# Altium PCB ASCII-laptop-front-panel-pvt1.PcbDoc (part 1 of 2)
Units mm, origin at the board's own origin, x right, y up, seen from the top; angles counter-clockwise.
Board outline 38.68 x 84.1 mm, 4 copper layers (Top Layer, Internal Plane 1, Internal Plane 2, Bottom Layer), stack 1.573 mm thick; 37 components, 33 nets, 674 pads, 57 vias.
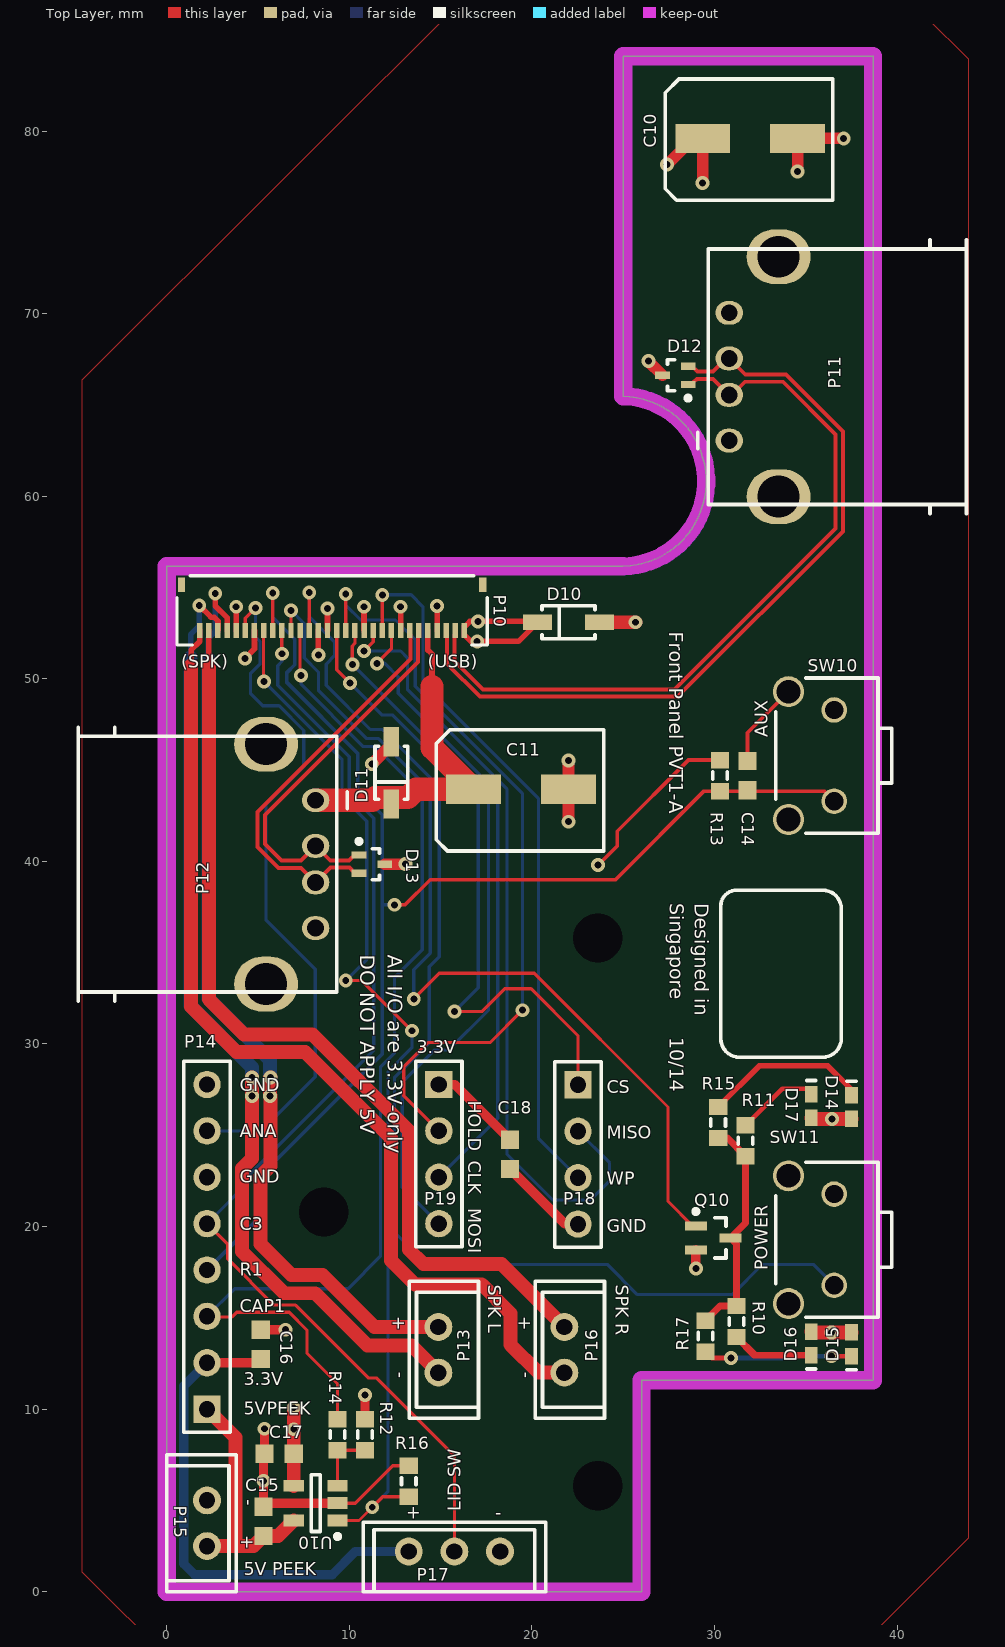
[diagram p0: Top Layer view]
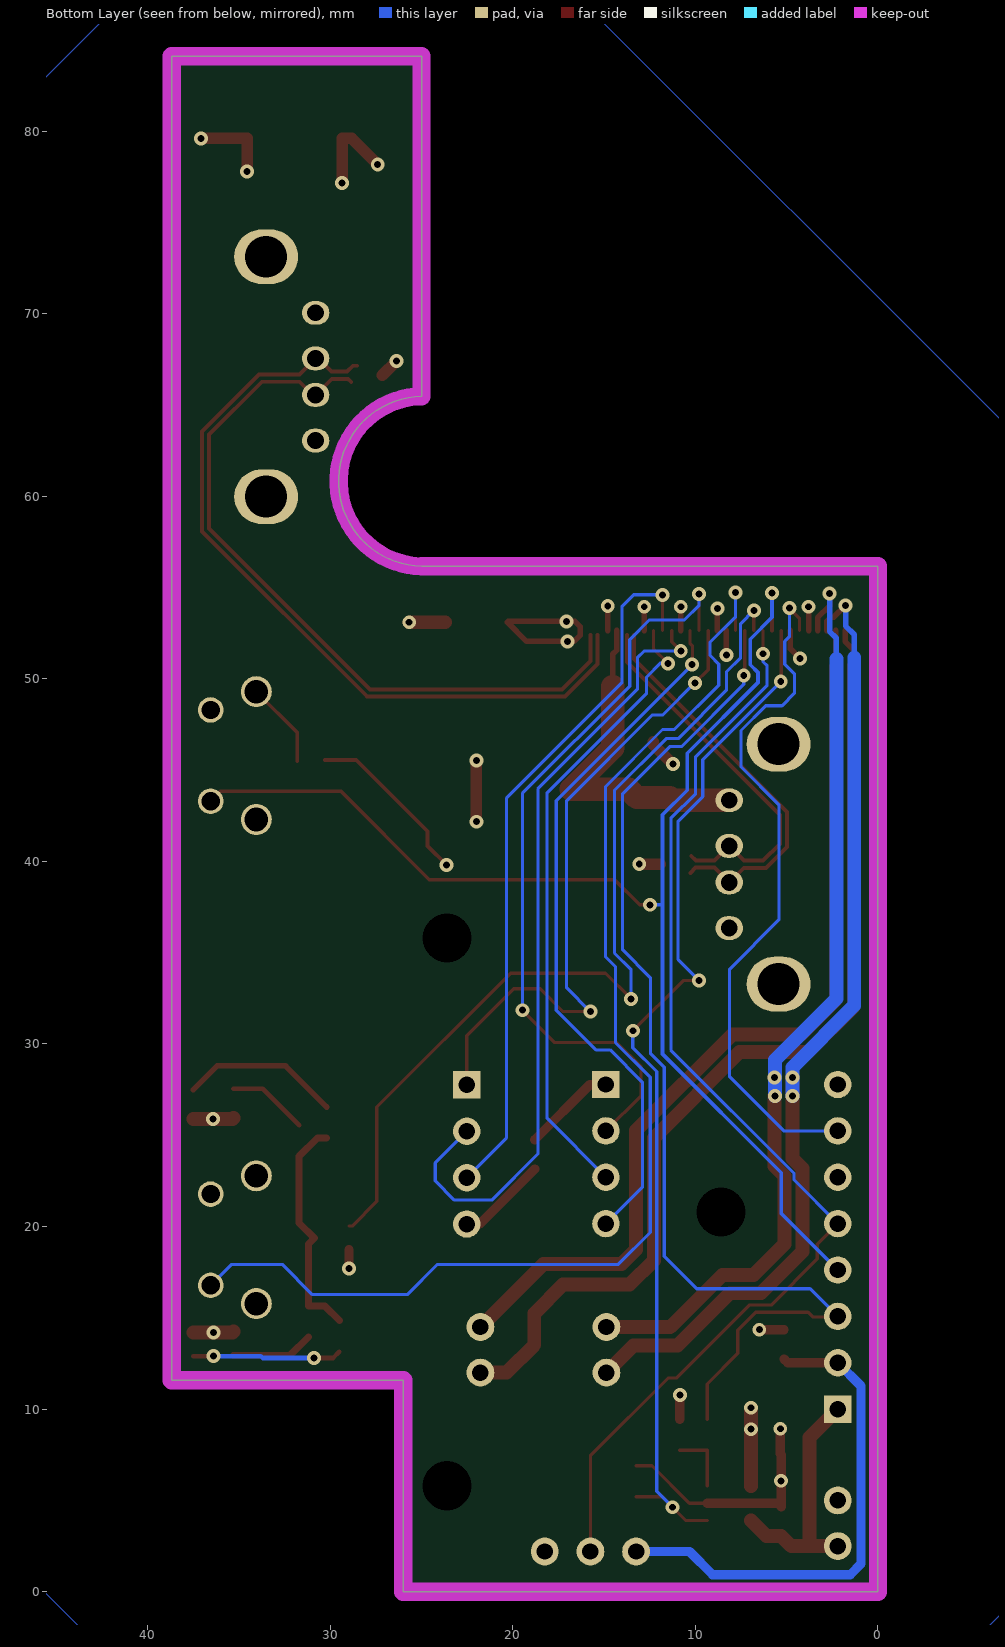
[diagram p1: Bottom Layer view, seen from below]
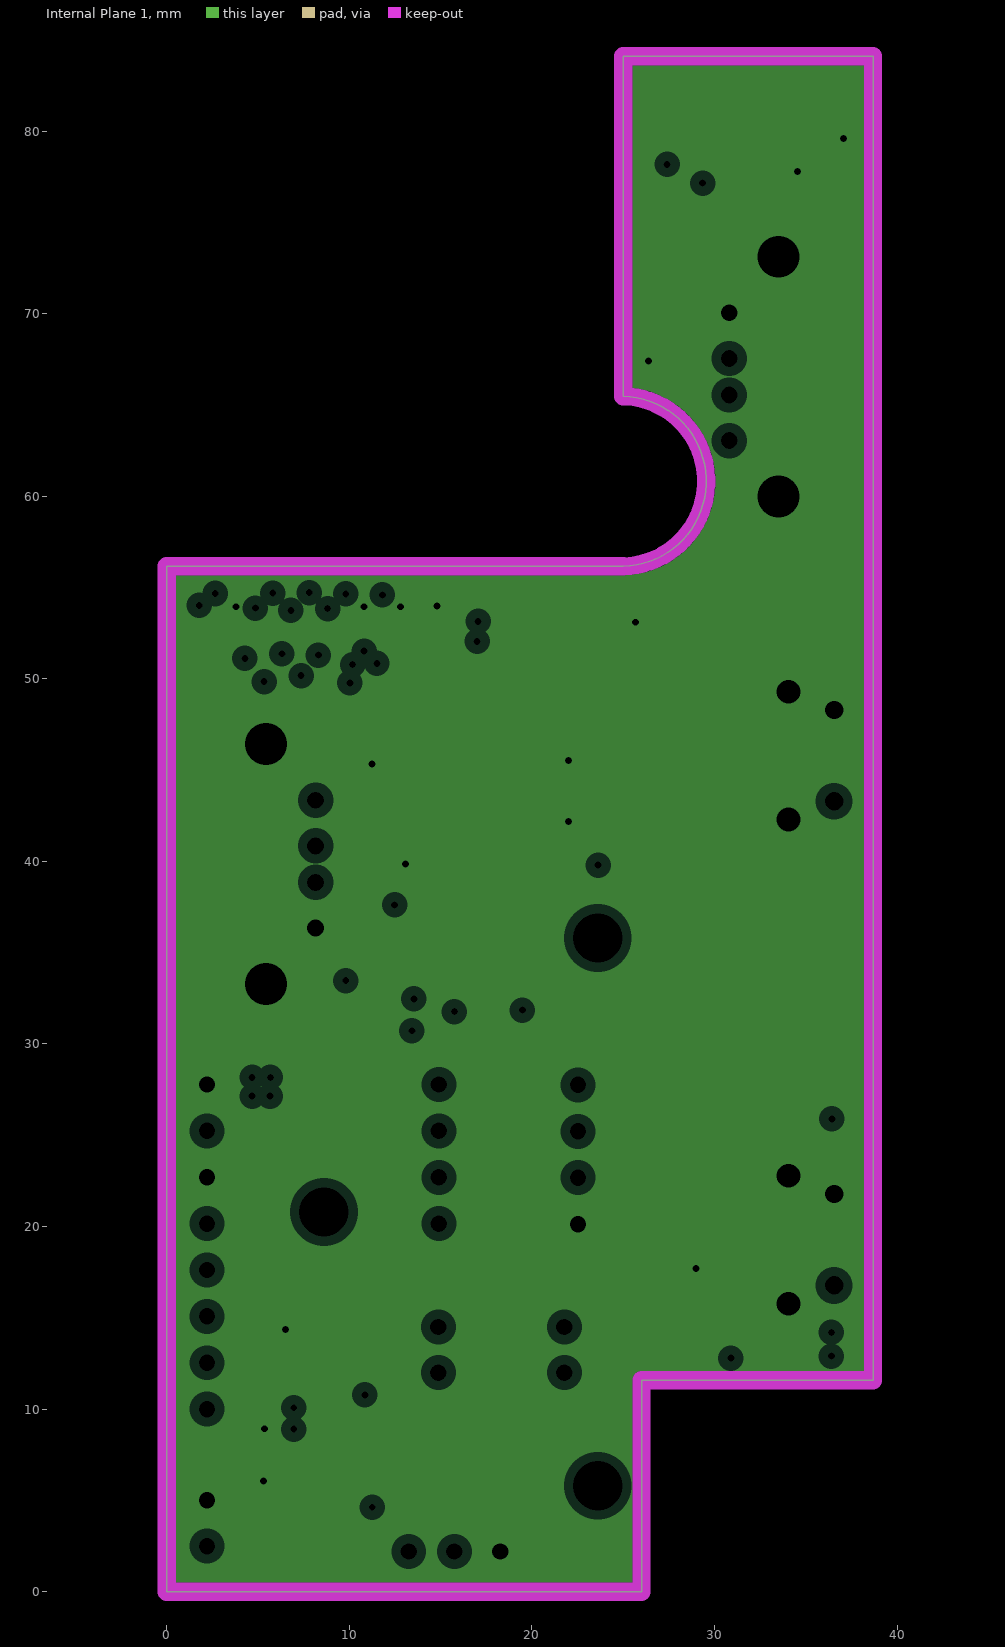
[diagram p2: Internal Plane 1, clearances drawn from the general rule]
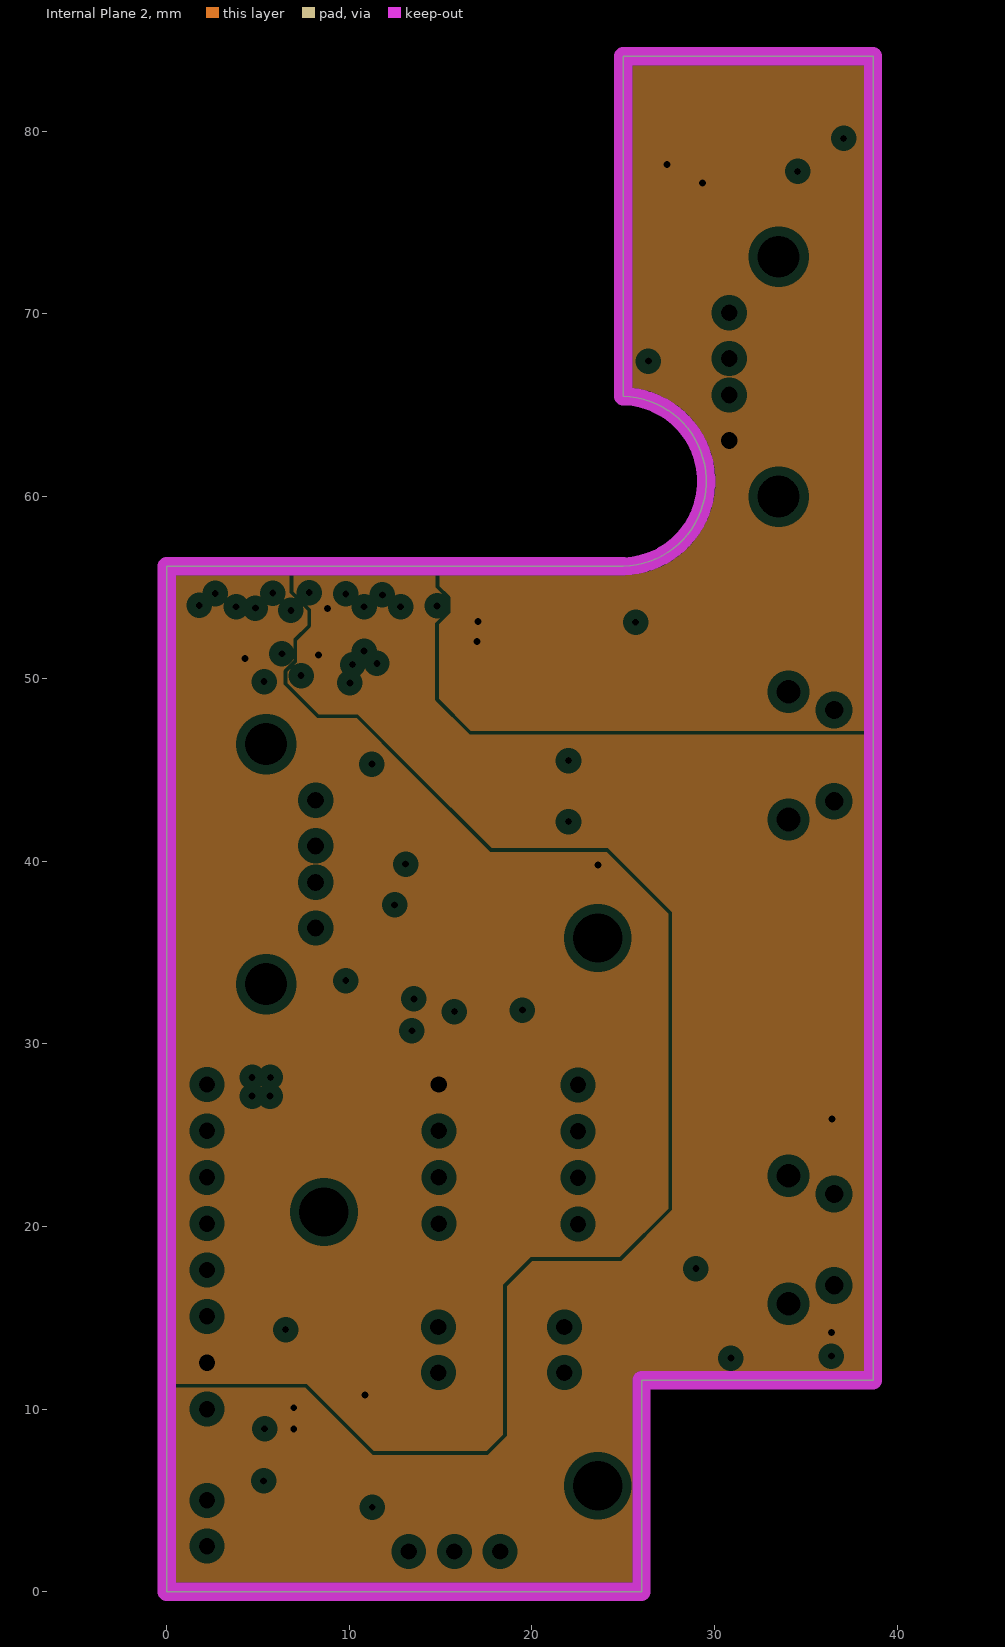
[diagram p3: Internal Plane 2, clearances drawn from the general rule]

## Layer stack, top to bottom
Top Solder: solder mask 0.0102, Solder Resist, Dk 3.5
Top Layer: signal copper 0.0356
Dielectric 1: core 0.165, FR-4, Dk 4.2
Internal Plane 1: plane copper 0.036, net GND
Dielectric 3: prepreg 1.1, Dk 4.2
Internal Plane 2: plane copper 0.036, net (Multiple Nets)
Dielectric 2: core 0.165, Dk 4.2
Bottom Layer: signal copper 0.0356
Bottom Solder: solder mask 0.0102, Solder Resist, Dk 3.5

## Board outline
0,0 0,56.161 24.997,56.161 ccw(c24.881,60.822) 24.997,65.483 24.997,82.115 24.997,84.099 38.685,84.099 38.685,11.581 26,11.581 26,0

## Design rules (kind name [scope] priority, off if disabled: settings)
AssemblyTestPointUsage [All] p0: scope1count=1 scope1_0_kind=Board scope1_0_value=Board scope2count=1 scope2_0_kind=Board scope2_0_value=Board commentlength=0
AssemblyTestpoint [All] p0: scope1count=1 scope1_0_kind=Board scope1_0_value=Board scope2count=1 scope2_0_kind=Board scope2_0_value=Board commentlength=0
Clearance Clearance_1 [All] p0 off: scope1count=1 scope1_0_kind=Board scope1_0_value=Board scope2count=1 scope2_0_kind=Board scope2_0_value=Board commentlength=88 gap=0.889 // Protel DXP Scope 2 Expression Was: InDifferentialPairClass('All Differential Pairs')
Clearance Clearance_NPTH [All] p0 off: scope1count=1 scope1_0_kind=Board scope1_0_value=Board scope2count=1 scope2_0_kind=Board scope2_0_value=Board commentlength=60 gap=0.381 // Protel DXP Scope 1 Expression Was: PadIsPlated = 'False'
Clearance [All] p0: scope1count=1 scope1_0_kind=Board scope1_0_value=Board scope2count=1 scope2_0_kind=Board scope2_0_value=Board commentlength=0 gap=0.178
Clearance Clearance_1 [InPoly vs InDifferentialPairClass('All Differential Pairs')] p1: gap=0.889
Clearance Clearance_NPTH [PadIsPlated = 'False'] p2: gap=0.381
Clearance [All] p3: gap=0.178
ComponentClearance [All] p0 off: scope1count=1 scope1_0_kind=Board scope1_0_value=Board scope2count=1 scope2_0_kind=Board scope2_0_value=Board commentlength=0 gap=0.254 collisioncheckmode=3
ComponentClearance [All] p1 off: gap=0.254 collisioncheckmode=3 verticalgap=0.254 showdistances=FALSE
DiffPairsRouting [All] p0: scope1count=1 scope1_0_kind=Board scope1_0_value=Board scope2count=1 scope2_0_kind=Board scope2_0_value=Board commentlength=0
DiffPairsRouting [All] p1: maxlimit=0.508 minlimit=0.178 mostfreqgap=0.178 toplayer_minwidth=0.216 toplayer_maxwidth=0.216 toplayer_prefwidth=0.216 bottomlayer_minwidth=0.216 bottomlayer_maxwidth=0.216 bottomlayer_prefwidth=0.216 maxuncoupledlength=12.7
FabricationTestPointUsage [All] p0: scope1count=1 scope1_0_kind=Board scope1_0_value=Board scope2count=1 scope2_0_kind=Board scope2_0_value=Board commentlength=0 valid=0 allowmultiple=FALSE
FabricationTestpoint [All] p0: scope1count=1 scope1_0_kind=Board scope1_0_value=Board scope2count=1 scope2_0_kind=Board scope2_0_value=Board commentlength=0 side=3 testpointundercomponent=TRUE minsize=1.016 maxsize=2.54 preferedsize=1.524 minholesize=0 maxholesize=1.016 preferedholesize=0.813 testpointgrid=0.025
FanoutControl Fanout_Default [All] p0: scope1count=1 scope1_0_kind=Board scope1_0_value=Board scope2count=1 scope2_0_kind=Board scope2_0_value=Board commentlength=30 // Fanout_Default (Default Rule)
FanoutControl Fanout_Small [All] p0 off: scope1count=1 scope1_0_kind=Board scope1_0_value=Board scope2count=1 scope2_0_kind=Board scope2_0_value=Board commentlength=84 // Protel DXP Scope 1 Expression Was: (CompPinCount < 5)   Fanout_Small (Default Rule)
FanoutControl Fanout_SOIC [All] p0 off: scope1count=1 scope1_0_kind=Board scope1_0_value=Board scope2count=1 scope2_0_kind=Board scope2_0_value=Board commentlength=71 // Protel DXP Scope 1 Expression Was: IsSOIC   Fanout_SOIC (Default Rule)
FanoutControl Fanout_LCC [All] p0 off: scope1count=1 scope1_0_kind=Board scope1_0_value=Board scope2count=1 scope2_0_kind=Board scope2_0_value=Board commentlength=69 // Protel DXP Scope 1 Expression Was: IsLCC   Fanout_LCC (Default Rule)
FanoutControl Fanout_BGA [All] p0 off: scope1count=1 scope1_0_kind=Board scope1_0_value=Board scope2count=1 scope2_0_kind=Board scope2_0_value=Board commentlength=69 // Protel DXP Scope 1 Expression Was: IsBGA   Fanout_BGA (Default Rule)
Height [All] p0: scope1count=1 scope1_0_kind=Board scope1_0_value=Board scope2count=1 scope2_0_kind=Board scope2_0_value=Board commentlength=0
HoleSize [All] p0: scope1count=1 scope1_0_kind=Board scope1_0_value=Board scope2count=1 scope2_0_kind=Board scope2_0_value=Board commentlength=0 absolutevalues=TRUE maxlimit=6.35 minlimit=0.025 maxpercent=80.000 minpercent=20.000
HoleSize [All] p1: absolutevalues=TRUE maxlimit=6.35 minlimit=0.025 maxpercent=80.000 minpercent=20.000
HoleToHoleClearance [All] p0: scope1count=1 scope1_0_kind=Board scope1_0_value=Board scope2count=1 scope2_0_kind=Board scope2_0_value=Board commentlength=0
LayerPairs [All] p0: scope1count=1 scope1_0_kind=Board scope1_0_value=Board scope2count=1 scope2_0_kind=Board scope2_0_value=Board commentlength=0 enforce=TRUE
MinimumSolderMaskSliver [All] p0 off: scope1count=1 scope1_0_kind=Board scope1_0_value=Board scope2count=1 scope2_0_kind=Board scope2_0_value=Board commentlength=0
MinimumSolderMaskSliver [All] p1 off: minsoldermaskwidth=0.254
NetAntennae [All] p0: scope1count=1 scope1_0_kind=Board scope1_0_value=Board scope2count=1 scope2_0_kind=Board scope2_0_value=Board commentlength=0
PasteMaskExpansion [All] p0: scope1count=1 scope1_0_kind=Board scope1_0_value=Board scope2count=1 scope2_0_kind=Board scope2_0_value=Board commentlength=0 expansion=0
PlaneClearance [All] p0: scope1count=1 scope1_0_kind=Board scope1_0_value=Board scope2count=1 scope2_0_kind=Board scope2_0_value=Board commentlength=0 clearance=0.508
PlaneClearance [All] p1: clearance=0.508
PlaneConnect [All] p0: scope1count=1 scope1_0_kind=Board scope1_0_value=Board scope2count=1 scope2_0_kind=Board scope2_0_value=Board commentlength=0 planeconnectstyle=Direct reliefexpansion=0.508 reliefentries=4 reliefconductorwidth=0.254 reliefairgap=0.254
PlaneConnect [All] p1: planeconnectstyle=Direct reliefexpansion=0.508 reliefentries=4 reliefconductorwidth=0.254 reliefairgap=0.254
PolygonConnect [All] p0: scope1count=1 scope1_0_kind=Board scope1_0_value=Board scope2count=1 scope2_0_kind=Board scope2_0_value=Board commentlength=0 connectstyle=Relief reliefconductorwidth=0.508 reliefentries=4 polygonreliefangle="90 Angle"
PolygonConnect [All] p1: connectstyle=Relief reliefconductorwidth=0.508 reliefentries=4 polygonreliefangle="90 Angle" airgapwidth=0.254
RoomDefinition connectors [All] p0 off: scope1count=1 scope1_0_kind=ComponentClass scope1_0_value=connectors scope2count=1 scope2_0_kind=Board scope2_0_value=Board commentlength=0 region_x1=30316014 region_y1=15196820 region_x2=32047180 region_y2=17472985 confinementstyle=ConfineIn
RoomDefinition connectors [InComponentClass('connectors')] p1 off: confinementstyle=ConfineIn formatcopy=TRUE lockcomponents=FALSE outline 35.697,1.458 31.3,1.458 31.3,7.239 35.697,7.239
RoutingCorners [All] p0: scope1count=1 scope1_0_kind=Board scope1_0_value=Board scope2count=1 scope2_0_kind=Board scope2_0_value=Board commentlength=0 cornerstyle=45-Degree minsetback=2.54 maxsetback=2.54
RoutingLayers [All] p0: scope1count=1 scope1_0_kind=Board scope1_0_value=Board scope2count=1 scope2_0_kind=Board scope2_0_value=Board commentlength=0 top layer=Automatic bottom layer=Automatic
RoutingPriority [All] p0: scope1count=1 scope1_0_kind=Board scope1_0_value=Board scope2count=1 scope2_0_kind=Board scope2_0_value=Board commentlength=0
RoutingTopology [All] p0: scope1count=1 scope1_0_kind=Board scope1_0_value=Board scope2count=1 scope2_0_kind=Board scope2_0_value=Board commentlength=0 topology=Shortest
RoutingVias [All] p0: scope1count=1 scope1_0_kind=Board scope1_0_value=Board scope2count=1 scope2_0_kind=Board scope2_0_value=Board commentlength=0 holewidth=0.381 width=0.762 viastyle="Through Hole" minholewidth=0.381 minwidth=0.762 maxholewidth=0.381 maxwidth=0.762
RoutingVias [All] p1: holewidth=0.381 width=0.762 viastyle="Through Hole" minholewidth=0.381 minwidth=0.762 maxholewidth=0.381 maxwidth=0.762
ShortCircuit [All] p0: scope1count=1 scope1_0_kind=Board scope1_0_value=Board scope2count=1 scope2_0_kind=Board scope2_0_value=Board commentlength=0 allowed=FALSE
SilkToBoardRegionClearance [All] p0 off: scope1count=1 scope1_0_kind=Board scope1_0_value=Board scope2count=1 scope2_0_kind=Board scope2_0_value=Board commentlength=0
SilkToBoardRegionClearance [All] p1 off:
SilkToSilkClearance [All] p0 off: scope1count=1 scope1_0_kind=Board scope1_0_value=Board scope2count=1 scope2_0_kind=Board scope2_0_value=Board commentlength=0
SilkToSilkClearance [All] p1 off: silktosilkclearance=0.254
SilkToSolderMaskClearance [All] p0 off: scope1count=1 scope1_0_kind=Board scope1_0_value=Board scope2count=1 scope2_0_kind=Board scope2_0_value=Board commentlength=44 // Protel DXP Scope 1 Expression Was: IsPad
SilkToSolderMaskClearance [IsPad] p1 off: minsilkscreentomaskgap=0.254 clearancetoexposedcopper=TRUE
SolderMaskExpansion [All] p0: scope1count=1 scope1_0_kind=Board scope1_0_value=Board scope2count=1 scope2_0_kind=Board scope2_0_value=Board commentlength=0 expansion=0.076
SolderMaskExpansion [All] p1: expansion=0.076
UnRoutedNet [All] p0: scope1count=1 scope1_0_kind=Board scope1_0_value=Board scope2count=1 scope2_0_kind=Board scope2_0_value=Board commentlength=0
Width [All] p0: scope1count=1 scope1_0_kind=Board scope1_0_value=Board scope2count=1 scope2_0_kind=Board scope2_0_value=Board commentlength=0 maxlimit=2.54 minlimit=0.178 preferedwidth=0.254
Width [All] p1: maxlimit=2.54 minlimit=0.178 preferedwidth=0.254 minimp=50.000000 maximp=50.000000 favimp=50.000000
20 further rules are at their usual default settings.

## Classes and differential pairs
net class USB_NETS: USB_KBD_N USB_KBD_P USB_MOUSE_N USB_MOUSE_P
differential pair USB_MOUSE: +USB_MOUSE_P -USB_MOUSE_N
differential pair " ": +USB_KBD_P -USB_KBD_N

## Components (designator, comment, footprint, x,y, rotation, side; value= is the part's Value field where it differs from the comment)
C10 "100uF, 10V, VS D" ALCAP_D 31.95,79.6 r180 top
C11 "100uF, 10V, VS D" ALCAP_D 19.4,43.95 r180 top
C14 "0.1uF, 25V, X5R" CAPC1608N 31.8,44.7 r90 top
C15 "10uF, 10V, X5R, 20%" CAPC1608N 5.3,3.85 r90 top
C16 "10uF, 10V, X5R, 20%" CAPC1608N 5.15,13.55 r90 top
C17 "1.0uF, 25V, 20% X5R" CAPC1608N 6.15,7.55 r180 top
C18 "0.1uF, 25V, X5R" CAPC1608N 18.8,23.95 r270 top
D10 "RSA5M" SOD123/X.85 22,53.1 r0 top
D11 "RSA5M" SOD123/X.85 12.3,44.85 r90 top
D12 "RCLAMP0502B" SOT-523 27.85,66.625 r180 top
D13 "RCLAMP0502B" SOT-523 11.225,39.85 r0 top
D14 "WHITE 0402" CD1005-0402 37.5,26.55 r90 top
D15 "WHITE 0402" CD1005-0402 37.5,13.55 r270 top
D16 "WHITE 0402" CD1005-0402 35.3,13.6 r270 top
D17 "WHITE 0402" CD1005-0402 35.3,26.6 r90 top
P10 "HRS FH34SRJ-30S-0.5SH(99)" HRS_FH34SRJ-30S-0.5SH 9.55,52.65 r180 top
P11 "AUK USB-1X04-SR-BK-S-H" USB_TYPEA_TH_SINGLE 30.8,66.55 r90 top
P12 "AUK USB-1X04-SR-BK-S-H" USB_TYPEA_TH_SINGLE 8.15,39.85 r270 top
P13 "JST B2B-EH-A" JST_B2B_EH_A 14.875,12 r90 top
P14 "Header 8" HDR1X8 2.2,10 r90 top
P15 "JST B2B-EH-A" JST_B2B_EH_A 2.2,5 r270 top
P16 "JST B2B-EH-A" JST_B2B_EH_A 21.775,12 r90 top
P17 "JST B3B-EH-A" JST_B3B_EH_A 13.25,2.2 r0 top
P18 "Header 4" HDR1X4 22.52,27.757 r270 top
P19 "Header 4" HDR1X4 14.9,27.78 r270 top
Q10 "2N7002W" SOT323-3AN 29.925,19.375 r0 top
R10 "1k, 1%" RESC1608N 31.2,14.8 r270 top
R11 "1k, 1%" RESC1608N 31.7,24.7 r90 top
R12 "10k, 1%" RESC1608N 10.85,8.6 r270 top
R13 "10k, 1%" RESC1608N 30.3,44.7 r270 top
R14 "0 ohm (DNP)" RESC1608N 9.35,8.6 r90 top
R15 "1k, 1%" RESC1608N 30.2,25.7 r90 top
R16 "10k, 1%" RESC1608N 13.25,6.05 r90 top
R17 "1k, 1%" RESC1608N 29.5,14 r270 top
SW10 "PTS635-V-L-31" PTS635-V-X-31 36.551,45.796 r90 top
SW11 "PTS635-V-L-31" PTS635-V-X-31 36.551,19.279 r90 top
U10 "RT9706" SOT23-5AN 8.15,4.85 r180 top

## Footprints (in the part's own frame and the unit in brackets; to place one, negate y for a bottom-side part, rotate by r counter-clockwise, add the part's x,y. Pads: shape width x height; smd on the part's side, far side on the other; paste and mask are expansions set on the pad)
ALCAP_D [mm]
  rect 3x1.6 smd: 1(2.6,0) 2(-2.6,0)
  silkscreen extent -4.52,-3.25 4.65,3.38
CAPC1608N [mm] "Chip Capacitor, Body 1.6x0.8mm, IPC Medium Density"
  rect 1x1 smd: 1(-0.8,0) 2(0.8,0)
CD1005-0402 [mm] "Chip Diode; Body 1.0 x 0.5 mm (LxW typ)"
  rect 0.9x0.7 smd: 1(-0.65,0) 2(0.65,0)
  silkscreen extent 1.4,-0.25 1.4,0.25
HDR1X4 [mm] "Connector; Header; 4 Position"
  rect 1.5x1.5 hole 0.9: 1(0,0)
  round 1.5 hole 0.9: 2(2.54,0) 3(5.08,0) 4(7.62,0)
  silkscreen extent -1.27,-1.27 8.89,1.27
HDR1X8 [mm] "Connector; Header; 8 Position"
  rect 1.5x1.5 hole 0.9: 1(0,0)
  round 1.5 hole 0.9: 2(2.54,0) 3(5.08,0) 4(7.62,0) 5(10.16,0) 6(12.7,0) 7(15.24,0) 8(17.78,0)
  silkscreen extent -1.27,-1.27 19.05,1.27
HRS_FH34SRJ-30S-0.5SH [mm] "HRS 30-pin 0.5mm FFC/FPC"
  rect 0.4x0.8 smd: 0(-7.75,-2.5) 0(8.75,-2.5)
  rect 0.3x0.8 smd mask+0.07: 1(7.75,0) 2(7.25,0) 3(6.75,0) 4(6.25,0) 5(5.75,0) 6(5.25,0) 7(4.75,0) 8(4.25,0) 9(3.75,0) 10(3.25,0) 11(2.75,0) 12(2.25,0) 13(1.75,0) 14(1.25,0) 15(0.75,0) 16(0.25,0) 17(-0.25,0) 18(-0.75,0) 19(-1.25,0) 20(-1.75,0) 21(-2.25,0) 22(-2.75,0) 23(-3.25,0) 24(-3.75,0) 25(-4.25,0) 26(-4.75,0) 27(-5.25,0) 28(-5.75,0) 29(-6.25,0) 30(-6.75,0)
  silkscreen extent -8,-3 9,0.8
JST_B2B_EH_A [mil] "2-pin 2.5mm low cost connector"
  round 60 hole 35.43: 1(0,0) 2(98.42,0)
  silkscreen extent -98,-87 197,63
JST_B3B_EH_A [mil] "3-pin 2.5mm low cost connector"
  round 60 hole 35.43: 1(0,0) 2(98.43,0) 3(196.85,0)
  silkscreen extent -98,-87 295,63
PTS635-V-X-31 [mm] "Tact switch, right angle, through hole"
  round 1.7 hole 1.3 mask+0.07: 0(-3.5,2.5) 0(3.5,2.5)
  round 1.4 hole 1 mask+0.07: 1(-2.5,0) 2(2.5,0)
  silkscreen extent -4.25,-3.15 4.25,3.2
RESC1608N [mm] "Chip Resistor, Body 1.6x0.8mm, IPC Medium Density"
  rect 0.9x1 smd: 1(-0.85,0) 2(0.85,0)
  silkscreen extent -0.2,-0.4 0.2,0.4
SOD123/X.85 [mm] "SOD-123; 2 Leads; Body 2.7 x 1.6 mm, (LxW)"
  rect 1.6x0.85 smd: 1(-1.7,0) 2(1.7,0)
  silkscreen extent -1.45,-0.9 1.45,0.9
SOT23-5AN [mm] "SOT23, 5-Leads, Body 2.9x1.6mm, Pitch 0.95mm, Lead Span 2.8mm, IPC Medium Density"
  rect 1.1x0.65 smd mask+0.075: 1(-1.2,0.95) 2(-1.2,0) 3(-1.2,-0.95) 4(1.2,-0.95) 5(1.2,0.95)
  silkscreen extent -1.33,-1.55 0.25,1.95
SOT323-3AN [mm] "SOT323, 3-Leads, Body 2.0x1.3mm, Pitch 0.65mm, Lead Span 2.1mm, IPC Medium Density"
  rect 1.2x0.5 smd: 1(-0.95,0.65) 2(-0.95,-0.65) 3(0.95,0)
  silkscreen extent -1.07,-1.1 0.7,1.57
SOT-523 [mm] "SOT523/SC75, 3-Leads, Body 1.7x1.8mm (max), Pitch 0.50mm, IPC Medium Density"
  rect 0.8x0.4 smd: 1(-0.7,0.5) 2(-0.7,-0.5) 3(0.7,0)
  silkscreen extent -0.82,-0.85 0.43,1.37
USB_TYPEA_TH_SINGLE [mm] "USB Type A Female Through Hole, Right Angle"
  oval 3x3.5 hole 2.3 mask+0.07: 0(-6.57,-2.71) 0(6.57,-2.71)
  oval 1.3x1.5 hole 0.92 mask+0.07: 1(-3.5,0) 2(-1,0) 3(1,0) 4(3.5,0)
  silkscreen extent -7.5,-13 7.5,1.73

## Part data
C10 C11: library part "Cap Pol3", "Polarized Capacitor (Surface Mount)"
C14 C15 C16 C17 C18: library part "Cap Semi", "Capacitor (Semiconductor SIM Model)"
D10 D11: library part Tranzorb, "Tranzorb"
D12 D13: "2-channel ESD/CDE protection device for 5V devices"
D14 D15 D16 D17: library part LED2, "Green R/A LED, 0603 package"
P10: library part "Header 30", "Header, 30-Pin"
P11 P12: library part "Header 4", "Header, 4-Pin"
P13 P15 P16: library part "Header 2", "Header, 2-Pin"
P14: "Header, 8-Pin"
P17: library part "Header 3", "Header, 3-Pin"
P18 P19: "Header, 4-Pin"
Q10: library part MOSFET-N, "N-Channel MOSFET"
R10 R11 R12 R13 R14 R15 R16 R17: library part Res1, "Resistor"
SW10 SW11: library part SW-PB
U10: "IC LIN SW W/FLAG 500MA 2.0-5.5V SOT23-5"

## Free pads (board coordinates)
  round 2.5 hole 2.7 unplated mask+1.5: 0(8.6,20.8) 0(23.6,5.8) 0(23.6,35.8)
  rect 0.051x0.254 on Top Overlay: 1(30.823,33.571) 1(30.873,36.162) 1(31.331,30.167) 1(31.381,30.167) 1(31.432,30.167) 1(31.534,30.624) 1(31.889,37.736) 1(31.94,37.686) 1(31.991,34.434) 1(31.991,37.635) 1(32.042,37.584) 1(32.093,31.031) 1(32.093,37.533) 1(32.143,37.482) 1(32.194,32.91) 1(32.194,37.432) 1(32.347,37.33) 1(32.397,31.894) 1(32.397,37.279) 1(32.651,31.844) 1(32.702,31.844) 1(32.753,31.844) 1(32.804,31.844) 1(32.855,31.844) 1(32.905,31.844) 1(32.905,33.672) 1(32.956,31.844) 1(32.956,33.622) 1(33.261,35.196) 1(33.312,35.247) 1(33.363,35.298) 1(33.413,36.771) 1(33.515,31.64) 1(33.617,31.59) 1(33.667,31.539) 1(34.531,36.009) 1(34.937,35.45) 1(34.988,33.266) 1(34.988,35.349) 1(35.039,35.298) 1(35.09,31.59) 1(35.09,35.196) 1(35.09,37.635) 1(35.141,30.98) 1(35.141,35.146) 1(35.141,37.584) 1(35.191,31.437) 1(35.191,35.095) 1(35.191,37.482) 1(35.242,31.386) 1(35.242,36.365) 1(35.242,37.381) 1(35.293,36.365) 1(35.293,37.33) 1(35.344,36.416) 1(35.344,37.228) 1(35.395,32.707) 1(35.395,36.466) 1(35.395,37.178) 1(35.445,32.656) 1(35.445,36.517) 1(35.445,37.127) 1(35.496,32.555) 1(35.496,37.076) 1(35.547,32.504) 1(35.547,36.67) 1(35.547,37.025) 1(35.598,32.453) 1(35.649,32.402) 1(35.699,33.317) 1(35.699,36.873) 1(35.75,33.368) 1(35.75,36.822) 1(35.801,36.771) 1(35.903,33.571) 1(35.903,34.536) 1(35.903,36.72) 1(35.953,36.67) 1(36.055,36.619) 1(36.106,34.434) 1(36.157,33.114) 1(36.207,33.164) 1(36.309,32.402) 1(36.309,33.317) 1(36.309,34.993) 1(36.36,30.675) 1(36.36,32.453) 1(36.36,34.993) 1(36.411,35.044) 1(36.461,30.777)
  rect 0.051x0.203 on Top Overlay: 1(30.823,36.187) 1(31.483,30.193) 1(31.483,30.65) 1(31.839,37.762) 1(31.94,34.46) 1(33.413,31.717) 1(33.413,35.374) 1(33.464,30.599) 1(33.464,31.666) 1(33.464,36.797) 1(33.566,31.615) 1(34.226,31.31) 1(34.582,32.377) 1(34.887,35.527) 1(34.937,30.751) 1(35.039,31.666) 1(35.141,31.513) 1(35.191,31.056) 1(35.191,36.339) 1(35.242,35.019) 1(35.293,31.31) 1(35.293,34.968) 1(35.344,31.259) 1(35.344,34.917) 1(35.395,31.209) 1(35.395,34.866) 1(35.445,31.158) 1(35.496,31.107) 1(35.547,31.056) 1(35.598,31.005) 1(35.649,30.955) 1(35.649,33.291) 1(35.699,30.904) 1(35.699,32.326) 1(35.699,35.374) 1(35.75,32.275) 1(35.75,34.612) 1(35.801,32.225) 1(35.801,34.612) 1(35.852,31.463) 1(35.852,32.174) 1(35.852,34.561) 1(35.852,35.273) 1(35.852,36.746) 1(35.903,35.222) 1(35.953,34.511) 1(36.004,31.564) 1(36.004,34.46) 1(36.004,35.171) 1(36.004,36.644) 1(36.055,34.46) 1(36.055,35.12) 1(36.106,33.088) 1(36.207,35.069) 1(36.258,32.377) 1(36.258,35.019) 1(36.411,32.123) 1(36.411,32.529) 1(36.461,32.174) 1(36.563,32.275)
  rect 0.051x0.457 on Top Overlay: 1(30.873,33.469) 1(31.077,32.91) 1(31.127,32.809) 1(31.178,32.707) 1(32.296,34.485) 1(32.347,34.485) 1(32.397,34.536) 1(32.448,34.536) 1(32.499,34.587) 1(32.55,34.587) 1(32.601,34.638) 1(32.651,34.688) 1(32.753,34.739) 1(33.312,36.72) 1(33.413,33.012) 1(33.921,31.336) 1(34.328,32.402) 1(34.379,32.352) 1(34.429,35.908)
  rect 0.051x1.372 on Top Overlay: 1(30.924,30.777)
  rect 0.051x0.508 on Top Overlay: 1(30.924,33.342) 1(30.975,33.19) 1(31.026,33.037) 1(31.178,30.142) 1(33.21,36.746) 1(33.261,36.746) 1(33.972,31.259) 1(34.429,32.326) 1(35.09,33.241) 1(35.598,36.847) 1(35.699,34.815) 1(35.801,35.171)
  rect 0.051x0.356 on Top Overlay: 1(30.924,36.162) 1(31.28,30.167) 1(31.28,31.488) 1(31.28,36.009) 1(31.432,32.352) 1(31.483,32.301) 1(31.534,32.25) 1(31.585,32.25) 1(31.635,32.199) 1(31.686,30.675) 1(31.686,32.148) 1(31.788,32.098) 1(31.889,32.047) 1(31.991,30.929) 1(32.042,30.98) 1(32.093,34.434) 1(32.702,37.076) 1(32.855,36.974) 1(32.956,36.924) 1(33.007,34.942) 1(33.058,34.993) 1(33.058,36.873) 1(33.109,33.418) 1(33.159,33.368) 1(33.363,36.771) 1(33.464,33.012) 1(33.566,32.961) 1(33.617,32.91) 1(33.667,32.86) 1(33.718,32.809) 1(33.769,32.809) 1(33.82,31.437) 1(33.82,32.758) 1(33.871,31.386) 1(33.871,32.707) 1(33.921,32.707) 1(33.972,32.656) 1(34.125,32.555) 1(34.328,35.958) 1(34.48,35.958) 1(34.531,32.352) 1(35.039,30.777) 1(35.649,36.873) 1(35.75,34.993) 1(35.801,30.777) 1(35.852,33.52) 1(36.258,33.266) 1(36.411,30.726)
  rect 0.051x1.473 on Top Overlay: 1(30.975,30.777)
  rect 0.051x0.406 on Top Overlay: 1(30.975,36.136) 1(31.178,31.412) 1(31.229,30.142) 1(31.229,31.463) 1(31.229,32.631) 1(31.28,32.529) 1(31.28,36.593) 1(31.331,32.479) 1(31.381,32.428) 1(31.737,30.701) 1(31.788,30.701) 1(31.839,30.751) 1(31.889,30.802) 1(31.94,30.853) 1(32.143,34.46) 1(32.194,34.46) 1(32.245,34.46) 1(32.702,34.714) 1(32.804,34.765) 1(32.855,34.815) 1(32.905,34.866) 1(32.956,34.917) 1(33.007,36.898) 1(33.109,36.847) 1(33.159,36.797) 1(34.125,31.31) 1(34.175,32.529) 1(34.226,32.479) 1(34.277,32.428) 1(34.379,35.933) 1(34.48,32.326) 1(35.039,33.241) 1(35.09,30.802) 1(35.445,34.765) 1(35.496,34.714) 1(35.649,34.765) 1(35.75,30.802) 1(36.055,37.305) 1(36.106,35.019) 1(36.207,36.644)
  rect 0.051x1.626 on Top Overlay: 1(31.026,30.751)
  rect 0.051x0.559 on Top Overlay: 1(31.026,36.162)
  rect 0.051x1.676 on Top Overlay: 1(31.077,30.777)
  rect 0.051x0.61 on Top Overlay: 1(31.077,36.187) 1(35.141,33.19) 1(35.903,31.31) 1(36.207,34.561)
  rect 0.051x1.727 on Top Overlay: 1(31.127,30.751) 1(34.074,31.92)
  rect 0.051x0.762 on Top Overlay: 1(31.127,36.212) 1(36.106,37.127)
  rect 0.051x0.914 on Top Overlay: 1(31.178,36.289) 1(36.157,34.714)
  rect 0.051x0.965 on Top Overlay: 1(31.229,36.314)
  rect 0.051x0.305 on Top Overlay: 1(31.331,31.513) 1(31.331,35.984) 1(31.381,31.513) 1(31.381,35.984) 1(31.432,31.513) 1(31.432,35.984) 1(31.483,31.513) 1(31.483,35.984) 1(31.534,31.513) 1(31.534,35.984) 1(31.585,30.65) 1(31.585,31.513) 1(31.585,35.984) 1(31.635,30.65) 1(31.635,31.513) 1(31.635,35.984) 1(31.686,31.513) 1(31.686,35.984) 1(31.737,31.513) 1(31.737,32.123) 1(31.737,35.984) 1(31.788,31.513) 1(31.788,35.984) 1(31.839,31.513) 1(31.839,32.072) 1(31.839,35.984) 1(31.889,31.513) 1(31.889,35.984) 1(31.94,31.513) 1(31.94,32.021) 1(31.94,35.984) 1(31.991,31.513) 1(31.991,32.021) 1(31.991,35.984) 1(32.042,31.513) 1(32.042,31.971) 1(32.042,34.46) 1(32.042,35.984) 1(32.093,31.513) 1(32.093,31.971) 1(32.093,35.984) 1(32.143,31.513) 1(32.143,31.971) 1(32.143,35.984) 1(32.194,31.513) 1(32.194,31.92) 1(32.194,35.984) 1(32.245,31.513) 1(32.245,31.92) 1(32.245,32.885) 1(32.245,35.984) 1(32.245,37.406) 1(32.296,30.599) 1(32.296,31.513) 1(32.296,31.92) 1(32.296,32.885) 1(32.296,35.984) 1(32.296,37.355) 1(32.347,30.599) 1(32.347,31.513) 1(32.347,31.92) 1(32.347,32.885) 1(32.347,35.984) 1(32.397,30.599) 1(32.397,31.513) 1(32.397,32.885) 1(32.397,35.984) 1(32.448,35.984) 1(32.448,37.254) 1(32.499,35.984) 1(32.499,37.203) 1(32.55,30.599) 1(32.55,31.869) 1(32.55,32.885) 1(32.55,35.984) 1(32.55,37.152) 1(32.601,30.599) 1(32.601,31.869) 1(32.601,32.885) 1(32.601,35.984) 1(32.601,37.152) 1(32.651,30.599) 1(32.651,32.885) 1(32.651,35.984) 1(32.651,37.101) 1(32.702,30.599) 1(32.702,32.885) 1(32.702,35.984) 1(32.753,30.599) 1(32.753,32.885) 1(32.753,35.984) 1(32.753,37.051) 1(32.804,30.599) 1(32.804,32.885) 1(32.804,35.984) 1(32.804,37) 1(32.855,30.599) 1(32.855,32.885) 1(32.855,35.984) 1(32.905,30.599) 1(32.905,32.885) 1(32.905,35.984) 1(32.905,36.949) 1(32.956,30.599) 1(32.956,32.885) 1(32.956,35.984) 1(33.007,30.599) 1(33.007,31.818) 1(33.007,32.885) 1(33.007,33.545) 1(33.007,35.984) 1(33.058,30.599) 1(33.058,31.818) 1(33.058,32.885) 1(33.058,33.495) 1(33.058,35.984) 1(33.109,30.599) 1(33.109,31.818) 1(33.109,32.885) 1(33.109,35.069) 1(33.109,35.984) 1(33.159,30.599) 1(33.159,31.818) 1(33.159,32.885) 1(33.159,35.12) 1(33.159,35.984) 1(33.21,30.599) 1(33.21,31.818) 1(33.21,32.885) 1(33.21,33.291) 1(33.21,35.171) 1(33.21,35.984) 1(33.261,35.984) 1(33.312,35.984) 1(33.363,35.984) 1(33.413,30.599) 1(33.413,35.984) 1(33.464,35.984) 1(33.515,32.987) 1(33.515,35.984) 1(33.566,35.984) 1(33.617,35.984) 1(33.667,35.984) 1(33.718,31.513) 1(33.718,35.984) 1(33.769,31.463) 1(33.769,35.984) 1(33.82,35.984) 1(33.871,35.984) 1(33.921,35.984) 1(33.972,35.984) 1(34.023,35.984) 1(34.074,35.984) 1(34.125,35.984) 1(34.175,31.31) 1(34.175,35.984) 1(34.226,35.984) 1(34.277,35.984) 1(34.988,30.751) 1(35.191,32.987) 1(35.242,32.936) 1(35.293,32.834) 1(35.344,32.783) 1(35.496,36.593) 1(35.547,34.714) 1(35.598,34.714) 1(35.801,33.393) 1(35.852,30.751) 1(35.903,30.751) 1(36.055,30.142) 1(36.106,36.543) 1(36.512,32.225)
  rect 0.051x0.102 on Top Overlay: 1(31.432,30.65) 1(32.143,32.987) 1(32.855,33.698) 1(33.515,36.847) 1(34.887,30.751) 1(35.039,37.711) 1(35.191,33.444) 1(35.242,33.444) 1(35.445,35.628) 1(36.055,31.615) 1(36.055,32.021) 1(36.157,32.326) 1(36.207,37.508) 1(36.258,36.593) 1(36.461,32.58)
  rect 0.051x0.152 on Top Overlay: 1(31.534,30.167) 1(31.585,30.167) 1(31.635,30.167) 1(31.686,30.167) 1(31.737,30.167) 1(31.788,30.167) 1(31.839,30.167) 1(31.889,30.167) 1(31.889,34.434) 1(31.94,30.167) 1(32.143,31.082) 1(32.245,30.675) 1(33.464,35.4) 1(33.515,30.624) 1(34.582,36.06) 1(34.633,32.402) 1(34.937,33.266) 1(35.141,30.675) 1(35.141,36.314) 1(35.191,30.675) 1(35.242,30.675) 1(35.293,30.675) 1(35.344,30.675) 1(35.395,30.675) 1(35.445,30.675) 1(35.496,30.675) 1(35.496,35.603) 1(35.547,30.675) 1(35.547,35.552) 1(35.598,30.675) 1(35.598,35.501) 1(35.649,30.675) 1(35.649,35.45) 1(35.699,30.675) 1(35.75,35.349) 1(35.903,32.148) 1(35.953,32.098) 1(35.953,35.196) 1(36.004,32.047) 1(36.004,37.33) 1(36.055,30.675) 1(36.055,33.063) 1(36.106,30.675) 1(36.157,30.675) 1(36.207,30.675) 1(36.207,32.352) 1(36.258,30.675) 1(36.258,34.434) 1(36.309,30.675) 1(36.36,32.098) 1(36.461,35.095)
  rect 0.051x2.591 on Top Overlay: 1(32.448,31.742) 1(32.499,31.742)
  rect 0.051x2.997 on Top Overlay: 1(33.261,31.894) 1(33.312,31.844)
  rect 0.051x2.946 on Top Overlay: 1(33.363,31.818)
  rect 0.051x0.051 on Top Overlay: 1(33.515,35.4) 1(34.277,31.336) 1(34.836,35.552) 1(34.988,31.691) 1(35.242,31.082) 1(36.309,32.098)
  rect 0.051x1.778 on Top Overlay: 1(34.023,31.894) 1(35.953,30.777)
  rect 0.051x1.27 on Top Overlay: 1(36.004,30.574)
  rect 0.051x1.118 on Top Overlay: 1(36.157,37)

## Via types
v1: diameter 0.762, hole 0.381, Top Layer to Bottom Layer, tented top, 57 vias

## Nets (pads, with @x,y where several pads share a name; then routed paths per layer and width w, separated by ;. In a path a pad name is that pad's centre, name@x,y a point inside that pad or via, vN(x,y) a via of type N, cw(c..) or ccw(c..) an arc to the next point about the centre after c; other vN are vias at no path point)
CHG_PWRSWITCH: P10.13 SW11.1 | length 68.5
  Top Layer w0.178: P10.13@7.8,52.65 v1(7.8,54.725)
  Bottom Layer w0.178: v1(7.8,54.725) 7.8,53.4 9.2,52 9.2,51.284 8.725,50.809 8.725,49.65 11.15,47.225 11.8,47.225 14.925,44.1 14.925,34.775 14.375,34.225 14.375,30.075 12.475,28.175 12.475,19.675 14.225,17.925 24.125,17.925 25.775,16.275 30.975,16.275 32.625,17.925 35.404,17.925 SW11.1@36.551,16.779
